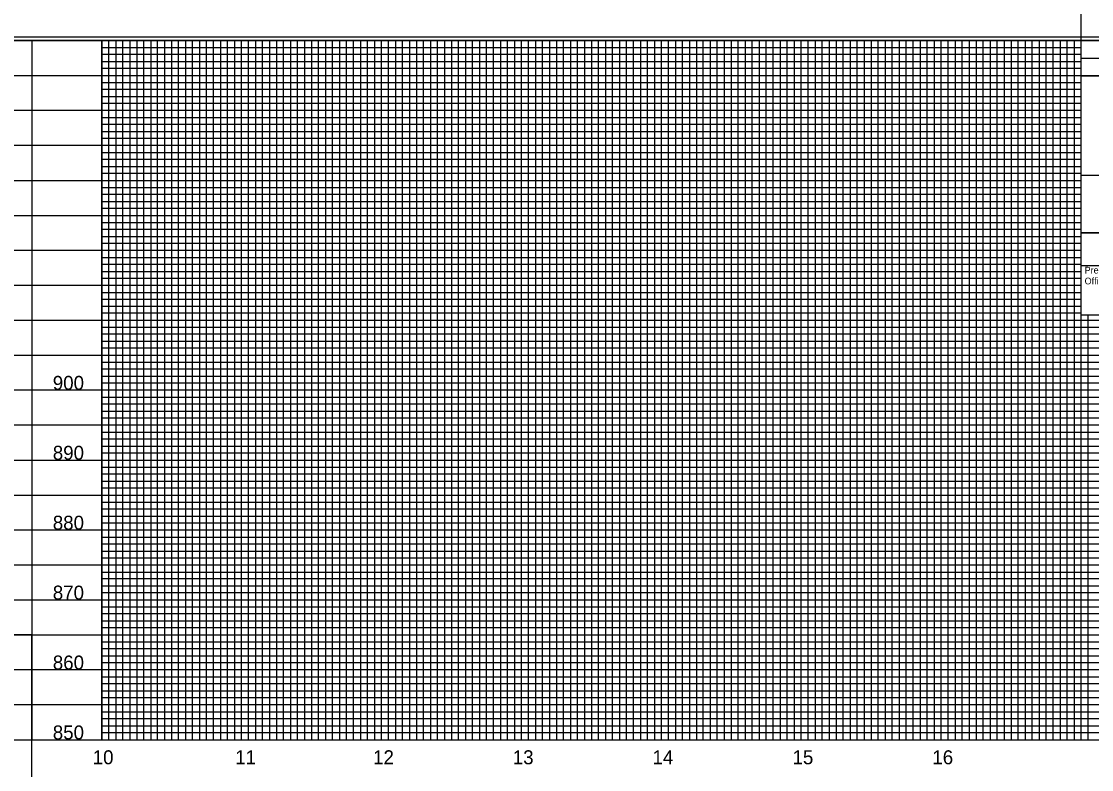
# Model space of a CAD drawing. Extents: x 1967929 to 1975641, y 546296 to 568534.
# Drawn here: x 1970574 to 1971339, y 566888 to 567423 of the extents above; entities that cross this region are included whole.
import ezdxf

# ---------------------------------------------------------------- set-up
doc = ezdxf.new("R2010")
doc.units = 0
for name, color, linetype in [('Exist Vertical Profile Horizontal Axis Label Major', 7, 'Continuous'), ('Exist Vertical Profile Vertical Axis Label', 7, 'Continuous'), ('Old_Level_2', 7, 'Continuous'), ('Old_Level_42', 7, 'Continuous'), ('Scratch_Level_1', 7, 'Continuous'), ('Scratch_Level_3', 7, 'Continuous'), ('Sheet Plot Border Inside CELL', 7, 'Continuous'), ('Sheet Profile CELL', 7, 'Continuous'), ('Sheet Profile Grid Major CELL', 7, 'Continuous'), ('Sheet Profile Grid Middle CELL', 7, 'Continuous'), ('Sheet Profile Grid Minor CELL', 7, 'Continuous')]:
    doc.layers.add(name, color=color, linetype=linetype)

msp = doc.modelspace()

# ---------------------------------------------------------------- linework, layer by layer
at = {"layer": 'Old_Level_42'}
msp.add_lwpolyline([(1971531.45, 567212.51), (1971331.4, 567212.51), (1971331.4, 567247.81)], dxfattribs=at)
at = {"layer": 'Scratch_Level_1'}
for p, q in [((1971331.4, 567247.81), (1971331.4, 567271.31)), ((1971331.4, 567271.31), (1971531.44, 567271.31)), ((1971531.44, 567247.81), (1971331.4, 567247.81))]:
    msp.add_line(p, q, dxfattribs=at)
at = {"layer": 'Scratch_Level_3'}
for points in [[(1970081.45, 567508.86), (1970081.45, 567008.86), (1971481.45, 567008.86), (1971481.5, 567312.53), (1971331.45, 567312.51), (1971331.4, 567508.86)], [(1970081.45, 567408.86), (1970081.45, 566908.86), (1971481.45, 566908.86), (1971481.5, 567212.51), (1971331.45, 567212.51), (1971331.4, 567408.86)], [(1970081.45, 567408.86), (1970081.45, 566908.86), (1971331.45, 566908.86), (1971331.45, 567177.21), (1971331.45, 567177.21), (1971331.45, 567408.86)], [(1970631.45, 567408.86), (1970631.45, 566908.86), (1971531.45, 566908.86), (1971531.45, 567212.52), (1971381.45, 567212.51), (1971381.45, 567408.86)], [(1970081.45, 566983.86), (1970081.45, 566483.86), (1970581.45, 566483.86), (1970581.45, 566683.86), (1970581.45, 566803.86), (1970581.45, 566983.86)]]:
    msp.add_lwpolyline(points, close=True, dxfattribs=at)
at = {"layer": 'Sheet Plot Border Inside CELL'}
msp.add_lwpolyline([(1969877.45, 566356.31), (1971543.95, 566356.31), (1971543.95, 567411.41), (1969877.45, 567411.41)], close=True, dxfattribs=at)
at = {"layer": 'Sheet Profile CELL'}
for p, q in [((1971331.4, 567396.31), (1971531.45, 567396.31)), ((1970031.45, 566908.86), (1971531.45, 566908.86))]:
    msp.add_line(p, q, dxfattribs=at)
for points in [[(1971531.45, 567408.86), (1970031.45, 567408.86), (1970031.45, 566358.86), (1971531.45, 566358.86)], [(1971331.4, 567408.86), (1971531.45, 567408.86), (1971531.45, 567383.81), (1971331.4, 567383.81)], [(1971331.4, 567383.81), (1971431.45, 567383.81), (1971431.45, 567271.31), (1971331.4, 567271.31)]]:
    msp.add_lwpolyline(points, close=True, dxfattribs=at)
msp.add_lwpolyline([(1971531.45, 567212.51), (1971331.4, 567212.51), (1971331.4, 567247.81)], dxfattribs=at)
at = {"layer": 'Sheet Profile Grid Major CELL'}
for points in [[(1971331.45, 567358.86), (1970031.45, 567358.86), (1970031.45, 567408.86), (1971331.45, 567408.86)], [(1970581.45, 567408.86), (1970581.45, 566908.86), (1970631.45, 566908.86), (1970631.45, 567408.86)], [(1970681.45, 567408.86), (1970681.45, 566908.86), (1970731.45, 566908.86), (1970731.45, 567408.86)], [(1970781.45, 567408.86), (1970781.45, 566908.86), (1970831.45, 566908.86), (1970831.45, 567408.86)], [(1970881.45, 567408.86), (1970881.45, 566908.86), (1970931.45, 566908.86), (1970931.45, 567408.86)], [(1970981.45, 567408.86), (1970981.45, 566908.86), (1971031.45, 566908.86), (1971031.45, 567408.86)], [(1971081.45, 567408.86), (1971081.45, 566908.86), (1971131.45, 566908.86), (1971131.45, 567408.86)], [(1971181.45, 567408.86), (1971181.45, 566908.86), (1971231.45, 566908.86), (1971231.45, 567408.86)], [(1971281.45, 567408.86), (1971281.45, 566908.86), (1971331.45, 566908.86), (1971331.45, 567408.86)], [(1971331.45, 567258.86), (1970031.45, 567258.86), (1970031.45, 567308.86), (1971331.45, 567308.86)], [(1971531.45, 567158.86), (1970031.45, 567158.86), (1970031.45, 567208.86), (1971331.4, 567208.86)], [(1971531.45, 567158.86), (1970031.45, 567158.86), (1970031.45, 567208.86), (1971531.45, 567208.86)], [(1971531.45, 567058.86), (1970031.45, 567058.86), (1970031.45, 567108.86), (1971531.45, 567108.86)], [(1971531.45, 566958.86), (1970031.45, 566958.86), (1970031.45, 567008.86), (1971531.45, 567008.86)]]:
    msp.add_lwpolyline(points, dxfattribs=at)
at = {"layer": 'Sheet Profile Grid Middle CELL'}
for points in [[(1970031.45, 567408.86), (1970031.45, 567383.86), (1971331.45, 567383.86)], [(1970656.45, 567408.86), (1970656.45, 566908.86), (1970706.45, 566908.86), (1970706.45, 567408.86)], [(1970756.45, 567408.86), (1970756.45, 566908.86), (1970806.45, 566908.86), (1970806.45, 567408.86)], [(1970856.45, 567408.86), (1970856.45, 566908.86), (1970906.45, 566908.86), (1970906.45, 567408.86)], [(1970956.45, 567408.86), (1970956.45, 566908.86), (1971006.45, 566908.86), (1971006.45, 567408.86)], [(1971056.45, 567408.86), (1971056.45, 566908.86), (1971106.45, 566908.86), (1971106.45, 567408.86)], [(1971156.45, 567408.86), (1971156.45, 566908.86), (1971206.45, 566908.86), (1971206.45, 567408.86)], [(1971256.45, 567408.86), (1971256.45, 566908.86), (1971306.45, 566908.86), (1971306.45, 567408.86)], [(1971331.45, 567333.86), (1970031.45, 567333.86), (1970031.45, 567283.86), (1971331.45, 567283.86)], [(1971331.45, 567233.86), (1970031.45, 567233.86), (1970031.45, 567183.86), (1971331.4, 567183.86)], [(1971331.45, 567233.86), (1970031.45, 567233.86), (1970031.45, 567183.86), (1971531.45, 567183.86)], [(1971531.45, 567133.86), (1970031.45, 567133.86), (1970031.45, 567083.86), (1971531.45, 567083.86)], [(1971531.45, 567033.86), (1970031.45, 567033.86), (1970031.45, 566983.86), (1971531.45, 566983.86)], [(1971531.45, 566933.86), (1970031.45, 566933.86)]]:
    msp.add_lwpolyline(points, dxfattribs=at)
at = {"layer": 'Sheet Profile Grid Minor CELL'}
msp.add_line((1970636.45, 566908.86), (1970636.45, 567408.86), dxfattribs=at)
for points in [[(1970641.45, 567408.86), (1970641.45, 566908.86), (1970641.45, 566908.86), (1970646.45, 566908.86), (1970646.45, 567408.86)], [(1970651.45, 567408.86), (1970651.45, 566908.86), (1970661.45, 566908.86), (1970661.45, 567408.86)], [(1970666.45, 567408.86), (1970666.45, 566908.86), (1970671.45, 566908.86), (1970671.45, 567408.86)], [(1970676.45, 567408.86), (1970676.45, 566908.86), (1970686.45, 566908.86), (1970686.45, 567408.86)], [(1970691.45, 567408.86), (1970691.45, 566908.86), (1970696.45, 566908.86), (1970696.45, 567408.86)], [(1970701.45, 567408.86), (1970701.45, 566908.86), (1970711.45, 566908.86), (1970711.45, 567408.86)], [(1970716.45, 567408.86), (1970716.45, 566908.86), (1970721.45, 566908.86), (1970721.45, 567408.86)], [(1970726.45, 567408.86), (1970726.45, 566908.86), (1970736.45, 566908.86), (1970736.45, 567408.86)], [(1970741.45, 567408.86), (1970741.45, 566908.86), (1970746.45, 566908.86), (1970746.45, 567408.86)], [(1970751.45, 567408.86), (1970751.45, 566908.86), (1970761.45, 566908.86), (1970761.45, 567408.86)], [(1970766.45, 567408.86), (1970766.45, 566908.86), (1970771.45, 566908.86), (1970771.45, 567408.86)], [(1970776.45, 567408.86), (1970776.45, 566908.86), (1970786.45, 566908.86), (1970786.45, 567408.86)], [(1970791.45, 567408.86), (1970791.45, 566908.86)], [(1970791.45, 566908.86), (1970796.45, 566908.86), (1970796.45, 567408.86)], [(1970801.45, 567408.86), (1970801.45, 566908.86), (1970811.45, 566908.86), (1970811.45, 567408.86)], [(1970816.45, 567408.86), (1970816.45, 566908.86), (1970821.45, 566908.86), (1970821.45, 567408.86)], [(1970826.45, 567408.86), (1970826.45, 566908.86), (1970836.45, 566908.86), (1970836.45, 567408.86)], [(1970841.45, 567408.86), (1970841.45, 566908.86), (1970846.45, 566908.86), (1970846.45, 567408.86)], [(1970851.45, 567408.86), (1970851.45, 566908.86), (1970861.45, 566908.86), (1970861.45, 567408.86)], [(1970866.45, 567408.86), (1970866.45, 566908.86), (1970871.45, 566908.86), (1970871.45, 567408.86)], [(1970876.45, 567408.86), (1970876.45, 566908.86), (1970886.45, 566908.86), (1970886.45, 567408.86)], [(1970891.45, 567408.86), (1970891.45, 566908.86), (1970896.45, 566908.86), (1970896.45, 567408.86)], [(1970901.45, 567408.86), (1970901.45, 566908.86), (1970911.45, 566908.86), (1970911.45, 567408.86)], [(1970916.45, 567408.86), (1970916.45, 566908.86), (1970921.45, 566908.86), (1970921.45, 567408.86)], [(1970926.45, 567408.86), (1970926.45, 566908.86), (1970936.45, 566908.86), (1970936.45, 567408.86)], [(1970941.45, 567408.86), (1970941.45, 566908.86), (1970946.45, 566908.86), (1970946.45, 567408.86)], [(1970951.45, 567408.86), (1970951.45, 566908.86), (1970961.45, 566908.86), (1970961.45, 567408.86)], [(1970966.45, 567408.86), (1970966.45, 566908.86), (1970971.45, 566908.86), (1970971.45, 567408.86)], [(1970976.45, 567408.86), (1970976.45, 566908.86), (1970986.45, 566908.86), (1970986.45, 567408.86)], [(1970991.45, 567408.86), (1970991.45, 566908.86), (1970996.45, 566908.86), (1970996.45, 567408.86)], [(1971001.45, 567408.86), (1971001.45, 566908.86), (1971011.45, 566908.86), (1971011.45, 567408.86)], [(1971016.45, 567408.86), (1971016.45, 566908.86), (1971021.45, 566908.86), (1971021.45, 567408.86)], [(1971026.45, 567408.86), (1971026.45, 566908.86), (1971036.45, 566908.86), (1971036.45, 567408.86)], [(1971041.45, 567408.86), (1971041.45, 566908.86), (1971046.45, 566908.86), (1971046.45, 567408.86)], [(1971051.45, 567408.86), (1971051.45, 566908.86), (1971061.45, 566908.86), (1971061.45, 567408.86)], [(1971066.45, 567408.86), (1971066.45, 566908.86), (1971071.45, 566908.86), (1971071.45, 567408.86)], [(1971076.45, 567408.86), (1971076.45, 566908.86), (1971086.45, 566908.86), (1971086.45, 567408.86)], [(1971091.45, 567408.86), (1971091.45, 566908.86), (1971096.45, 566908.86), (1971096.45, 567408.86)], [(1971101.45, 567408.86), (1971101.45, 566908.86)], [(1971101.45, 566908.86), (1971111.45, 566908.86), (1971111.45, 567408.86)], [(1971116.45, 567408.86), (1971116.45, 566908.86), (1971121.45, 566908.86), (1971121.45, 567408.86)], [(1971126.45, 567408.86), (1971126.45, 566908.86), (1971136.45, 566908.86), (1971136.45, 567408.86)], [(1971141.45, 567408.86), (1971141.45, 566908.86), (1971146.45, 566908.86), (1971146.45, 567408.86)], [(1971151.45, 567408.86), (1971151.45, 566908.86), (1971161.45, 566908.86), (1971161.45, 567408.86)], [(1971166.45, 567408.86), (1971166.45, 566908.86), (1971171.45, 566908.86), (1971171.45, 567408.86)], [(1971176.45, 567408.86), (1971176.45, 566908.86), (1971186.45, 566908.86), (1971186.45, 567408.86)], [(1971191.45, 567408.86), (1971191.45, 566908.86), (1971196.45, 566908.86), (1971196.45, 567408.86)], [(1971201.45, 567408.86), (1971201.45, 566908.86), (1971211.45, 566908.86), (1971211.45, 567408.86)], [(1971216.45, 567408.86), (1971216.45, 566908.86), (1971221.45, 566908.86), (1971221.45, 567408.86)], [(1971226.45, 567408.86), (1971226.45, 566908.86), (1971236.45, 566908.86), (1971236.45, 567408.86)], [(1971241.45, 567408.86), (1971241.45, 566908.86), (1971246.45, 566908.86), (1971246.45, 567408.86)], [(1971251.45, 567408.86), (1971251.45, 566908.86), (1971261.45, 566908.86), (1971261.45, 567408.86)], [(1971266.45, 567408.86), (1971266.45, 566908.86), (1971271.45, 566908.86), (1971271.45, 567408.86)], [(1971276.45, 567408.86), (1971276.45, 566908.86), (1971286.45, 566908.86), (1971286.45, 567408.86)], [(1971291.45, 567408.86), (1971291.45, 566908.86), (1971296.45, 566908.86), (1971296.45, 567408.86)], [(1971301.45, 567408.86), (1971301.45, 566908.86), (1971311.45, 566908.86), (1971311.45, 567408.86)], [(1971316.45, 567408.86), (1971316.45, 566908.86), (1971321.45, 566908.86), (1971321.45, 567408.86)], [(1971326.45, 567408.86), (1971326.45, 566908.86), (1971336.45, 566908.86), (1971336.45, 567177.21)], [(1971326.45, 567408.86), (1971326.45, 566908.86), (1971336.45, 566908.86), (1971336.45, 567212.51)], [(1970631.45, 567403.86), (1971331.45, 567403.86)], [(1971331.45, 567398.86), (1970631.45, 567398.86)], [(1970631.45, 567393.86), (1971331.45, 567393.86)], [(1971331.45, 567388.86), (1970631.45, 567388.86)], [(1970631.45, 567378.86), (1971331.45, 567378.86)], [(1971331.45, 567373.86), (1970631.45, 567373.86)], [(1970631.45, 567368.86), (1971331.45, 567368.86)], [(1971331.45, 567363.86), (1970631.45, 567363.86)], [(1970631.45, 567353.86), (1971331.45, 567353.86)], [(1971331.45, 567348.86), (1970631.45, 567348.86)], [(1970631.45, 567343.86), (1971331.45, 567343.86)], [(1971331.45, 567338.86), (1970631.45, 567338.86)], [(1970631.45, 567328.86), (1971331.45, 567328.86)], [(1971331.45, 567323.86), (1970631.45, 567323.86)], [(1970631.45, 567318.86), (1971331.45, 567318.86)], [(1971331.45, 567313.86), (1970631.45, 567313.86)], [(1970631.45, 567303.86), (1971331.45, 567303.86)], [(1971331.45, 567298.86), (1970631.45, 567298.86)], [(1970631.45, 567293.86), (1971331.45, 567293.86)], [(1971331.45, 567288.86), (1970631.45, 567288.86)], [(1970631.45, 567278.86), (1971331.45, 567278.86)], [(1971331.45, 567273.86), (1970631.45, 567273.86)], [(1970631.45, 567268.86), (1971331.45, 567268.86)], [(1971331.45, 567263.86), (1970631.45, 567263.86)], [(1970631.45, 567253.86), (1971331.45, 567253.86)], [(1971331.45, 567248.86), (1970631.45, 567248.86)], [(1970631.45, 567243.86), (1971331.45, 567243.86)], [(1971331.45, 567238.86), (1970631.45, 567238.86)], [(1970631.45, 567228.86), (1971331.45, 567228.86)], [(1971331.45, 567223.86), (1970631.45, 567223.86)], [(1970631.45, 567218.86), (1971331.45, 567218.86)], [(1971331.45, 567213.86), (1970631.45, 567213.86)], [(1970631.45, 567203.86), (1971331.4, 567203.86)], [(1970631.45, 567203.86), (1971481.45, 567203.86)], [(1971331.4, 567198.86), (1970631.45, 567198.86)], [(1971481.45, 567198.86), (1970631.45, 567198.86)], [(1970631.45, 567193.86), (1971331.4, 567193.86)], [(1970631.45, 567193.86), (1971481.45, 567193.86)], [(1971331.4, 567188.86), (1970631.45, 567188.86)], [(1971481.45, 567188.86), (1970631.45, 567188.86)], [(1970631.45, 567178.86), (1971331.4, 567178.86)], [(1970631.45, 567178.86), (1971481.45, 567178.86)], [(1971481.45, 567173.86), (1970631.45, 567173.86)], [(1970631.45, 567168.86), (1971481.45, 567168.86)], [(1971481.45, 567163.86), (1970631.45, 567163.86)], [(1970631.45, 567153.86), (1971481.45, 567153.86)], [(1971481.45, 567148.86), (1970631.45, 567148.86)], [(1970631.45, 567143.86), (1971481.45, 567143.86)], [(1971481.45, 567138.86), (1970631.45, 567138.86)], [(1970631.45, 567128.86), (1971481.45, 567128.86)], [(1971481.45, 567123.86), (1970631.45, 567123.86)], [(1970631.45, 567118.86), (1971481.45, 567118.86)], [(1971481.45, 567113.86), (1970631.45, 567113.86)], [(1970631.45, 567103.86), (1971481.45, 567103.86)], [(1971481.45, 567098.86), (1970631.45, 567098.86)], [(1970631.45, 567093.86), (1971481.45, 567093.86)], [(1971481.45, 567088.86), (1970631.45, 567088.86)], [(1970631.45, 567078.86), (1971481.45, 567078.86)], [(1971481.45, 567073.86), (1970631.45, 567073.86)], [(1970631.45, 567068.86), (1971481.45, 567068.86)], [(1971481.45, 567063.86), (1970631.45, 567063.86)], [(1970631.45, 567053.86), (1971481.45, 567053.86)], [(1971481.45, 567048.86), (1970631.45, 567048.86)], [(1970631.45, 567043.86), (1971481.45, 567043.86)], [(1971481.45, 567038.86), (1970631.45, 567038.86)], [(1970631.45, 567028.86), (1971481.45, 567028.86)], [(1971481.45, 567023.86), (1970631.45, 567023.86)], [(1970631.45, 567018.86), (1971481.45, 567018.86)], [(1971481.45, 567013.86), (1970631.45, 567013.86)], [(1970631.45, 567003.86), (1971481.45, 567003.86)], [(1971481.45, 566998.86), (1970631.45, 566998.86)], [(1970631.45, 566993.86), (1971481.45, 566993.86)], [(1971481.45, 566988.86), (1970631.45, 566988.86)], [(1970631.45, 566978.86), (1971481.45, 566978.86)], [(1971481.45, 566973.86), (1970631.45, 566973.86)], [(1970631.45, 566968.86), (1971481.45, 566968.86)], [(1971481.45, 566963.86), (1970631.45, 566963.86)], [(1970631.45, 566953.86), (1971481.45, 566953.86)], [(1971481.45, 566948.86), (1970631.45, 566948.86)], [(1970631.45, 566943.86), (1971481.45, 566943.86)], [(1971481.45, 566938.86), (1970631.45, 566938.86)], [(1970631.45, 566928.86), (1971481.45, 566928.86)], [(1971481.45, 566923.86), (1970631.45, 566923.86)], [(1970631.45, 566918.86), (1971481.45, 566918.86)], [(1970531.45, 566913.86), (1970081.45, 566913.86), (1970081.45, 566908.86), (1971481.45, 566908.86)], [(1971481.45, 566913.86), (1970631.45, 566913.86)]]:
    msp.add_lwpolyline(points, dxfattribs=at)

# ---------------------------------------------------------------- texts
at = {"layer": 'Exist Vertical Profile Horizontal Axis Label Major'}
for s, p in [('10', (1970625.03, 566891.36)), ('11', (1970726.87, 566891.36)), ('12', (1970825.42, 566891.36)), ('13', (1970925.26, 566891.36)), ('14', (1971025.1, 566891.36)), ('15', (1971125.19, 566891.36)), ('16', (1971225.13, 566891.36))]:
    msp.add_text(s, height=10, dxfattribs=at).set_placement(p)
at = {"layer": 'Exist Vertical Profile Vertical Axis Label'}
for s, p in [('900', (1970596.5, 567159.11)), ('890', (1970596.5, 567109.11)), ('880', (1970596.5, 567059.11)), ('870', (1970596.5, 567009.11)), ('860', (1970596.5, 566959.11)), ('850', (1970596.5, 566909.11))]:
    msp.add_text(s, height=10, dxfattribs=at).set_placement(p)
at = {"layer": 'Old_Level_2'}
for s, height, p in [('Prepared in the ', 4.8186, (1971333.95, 567242.31)), ('Office of:', 4.819, (1971333.95, 567234.56))]:
    msp.add_text(s, height=height, dxfattribs=at).set_placement(p)

doc.saveas('drawing.dxf')
